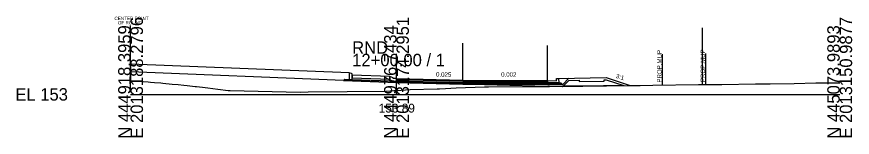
# Model space of a CAD drawing. Extents: x -26 to 163, y -10 to 7518.
# Drawn here: x -25.7 to 162.8, y 3990.3 to 4017.5 of the extents above; entities that cross this region are included whole.
import ezdxf

# ---------------------------------------------------------------- set-up
doc = ezdxf.new("R2010")
doc.units = 0
for name, color, linetype in [('Exist Cross Section Cell', 7, 'Continuous'), ('Exist XS Center Line Elevation Label', 7, 'Continuous'), ('Exist XS Ground Line', 7, 'Continuous'), ('Prop CMT Conc Surface', 7, 'Continuous'), ('Prop CMT Concrete Structures', 7, 'Continuous'), ('Prop CMT Pvmt Course 1', 7, 'Continuous'), ('Prop CMT Pvmt Course 1 CG', 7, 'Continuous'), ('Prop CMT Pvmt Course 2', 7, 'Continuous'), ('Prop CMT Pvmt Course 3', 7, 'Continuous'), ('Prop CMT Pvmt Surface', 7, 'Continuous'), ('Prop CMT Shear Line', 7, 'Continuous'), ('Prop CMT Shear Line Text', 7, 'Continuous'), ('Prop CMT Slope Grass', 7, 'Continuous'), ('Prop CMT Subgrade Earthwork', 7, 'Continuous'), ('Prop XS Earthwork Shape', 7, 'Continuous'), ('Prop XS Label Text', 7, 'Continuous'), ('Prop XS SE Text', 7, 'Continuous'), ('Prop XS Side Slope Text', 7, 'Continuous'), ('Scratch_Level_1', 7, 'Continuous')]:
    doc.layers.add(name, color=color, linetype=linetype)

msp = doc.modelspace()

# ---------------------------------------------------------------- linework, layer by layer
at = {"layer": 'Exist Cross Section Cell'}
for p, q in [((60, 4000), (60, 4009.16)), ((0, 4000), (60, 4000)), ((60, 4000), (160, 4000))]:
    msp.add_line(p, q, dxfattribs=at)
at = {"layer": 'Exist XS Ground Line'}
msp.add_lwpolyline([(0, 4003.05), (0.57, 4003.02), (1.73, 4002.95), (3.95, 4002.8), (4.51, 4002.76), (5.41, 4002.69), (6.86, 4002.58), (7.31, 4002.53), (9.41, 4002.32), (10.72, 4002.2), (11.98, 4002.07), (12.8, 4001.98), (14.56, 4001.8), (14.89, 4001.76), (16.21, 4001.62), (17.42, 4001.48), (19.69, 4001.2), (21.99, 4000.89), (22.46, 4000.88), (38.27, 4000.53), (40.04, 4000.58), (57.64, 4000.7), (59.4, 4000.86), (60, 4000.89), (63.11, 4001.07), (69.14, 4001.25), (69.71, 4001.28), (71.07, 4001.36), (73.47, 4001.46), (79.85, 4001.67), (80.43, 4001.69), (80.75, 4001.7), (90.04, 4001.77), (97.46, 4001.82), (99.61, 4001.83), (102.06, 4001.85), (112.76, 4001.99), (114.96, 4002.01), (117.85, 4002.05), (128.12, 4002.2), (133.39, 4002.25), (141.01, 4002.35), (144.34, 4002.37), (149.76, 4002.48), (154.62, 4002.57), (160, 4002.61)], dxfattribs=at)
at = {"layer": 'Prop CMT Conc Surface'}
for points in [[(50, 4004.54), (49.96, 4004.65), (49.85, 4004.69), (49.34, 4004.88)], [(50, 4004.38), (50, 4004.54)], [(60, 4003.58), (59.25, 4003.6), (59.25, 4003.77), (58.5, 4004.02)], [(94.09, 4003.16), (96.08, 4003.08)], [(96.08, 4003.08), (96.07, 4003.58), (96.57, 4003.59)]]:
    msp.add_lwpolyline(points, dxfattribs=at)
at = {"layer": 'Prop CMT Concrete Structures'}
for points in [[(50, 4004.54), (49.96, 4004.65), (49.85, 4004.69), (49.34, 4004.88)], [(49.34, 4004.88), (49.34, 4003.38)], [(50, 4004.38), (50, 4004.54)], [(49.34, 4003.38), (50, 4003.38)], [(50, 4003.38), (50, 4004.38)], [(50, 4004.38), (50, 4003.79)], [(58.5, 4004.02), (50, 4004.36)], [(50, 4003.77), (58.5, 4003.43)], [(60, 4003.58), (59.25, 4003.6), (59.25, 4003.77), (58.5, 4004.02)], [(58.5, 4004.02), (58.5, 4003.04)], [(58.5, 4003.43), (58.5, 4004.02)], [(58.5, 4003.04), (60, 4003)], [(60, 4003), (60, 4003.58)], [(94.09, 4003.16), (96.08, 4003.08), (96.07, 4003.58), (96.57, 4003.59)], [(96.57, 4003.59), (96.59, 4002.57), (94.09, 4002.58)], [(94.09, 4002.58), (94.09, 4003.16)]]:
    msp.add_lwpolyline(points, dxfattribs=at)
at = {"layer": 'Prop CMT Pvmt Course 1'}
for points in [[(60, 4003.58), (75, 4003.2)], [(60, 4003.33), (60, 4003.58)], [(75, 4002.95), (60, 4003.33)], [(75, 4003.2), (94.09, 4003.16)], [(94.09, 4002.91), (75.01, 4002.95)], [(94.09, 4003.16), (94.09, 4002.91)]]:
    msp.add_lwpolyline(points, dxfattribs=at)
msp.add_lwpolyline([(60, 4003.33), (60, 4003.46), (60, 4003.46), (60, 4003.33)], close=True, dxfattribs=at)
at = {"layer": 'Prop CMT Pvmt Course 1 CG'}
for points in [[(60, 4002.66), (60, 4003)], [(94.09, 4002.58), (97.09, 4002.57), (97.44, 4002.24)], [(94.09, 4002.24), (94.09, 4002.58)], [(97.52, 4002.24), (94.11, 4002.24)]]:
    msp.add_lwpolyline(points, dxfattribs=at)
at = {"layer": 'Prop CMT Pvmt Course 2'}
for points in [[(60, 4003), (60, 4003.33)], [(60, 4003.33), (75, 4002.95)], [(75, 4002.62), (60, 4003)], [(75.01, 4002.95), (94.09, 4002.91)], [(94.1, 4002.58), (75.01, 4002.62)], [(94.09, 4002.91), (94.09, 4002.58)]]:
    msp.add_lwpolyline(points, dxfattribs=at)
at = {"layer": 'Prop CMT Pvmt Course 3'}
for points in [[(50, 4003.38), (58.5, 4003.04)], [(60, 4003), (75, 4002.62)], [(60, 4002.66), (60, 4003)], [(75, 4002.29), (60, 4002.66)], [(75.01, 4002.62), (94.1, 4002.58)], [(94.09, 4002.58), (94.09, 4002.24)], [(94.11, 4002.24), (75.02, 4002.29)]]:
    msp.add_lwpolyline(points, dxfattribs=at)
at = {"layer": 'Prop CMT Pvmt Surface'}
for points in [[(60, 4003.58), (75, 4003.2)], [(75, 4003.2), (94.09, 4003.16)]]:
    msp.add_lwpolyline(points, dxfattribs=at)
at = {"layer": 'Prop CMT Shear Line'}
msp.add_line((0, 4000.52), (0, 4015.52), dxfattribs=at)
at = {"layer": 'Prop CMT Slope Grass'}
for p, q in [((49.34, 4004.86), (0, 4006.83)), ((48.06, 4003.14), (0, 4005.07))]:
    msp.add_line(p, q, dxfattribs=at)
for points in [[(96.57, 4003.59), (107.3, 4003.8)], [(107.3, 4003.8), (112.73, 4001.99)]]:
    msp.add_lwpolyline(points, dxfattribs=at)
at = {"layer": 'Prop CMT Subgrade Earthwork'}
for p, q in [((0, 4006.83), (0, 4003.05)), ((48.34, 4003.42), (48.06, 4003.14))]:
    msp.add_line(p, q, dxfattribs=at)
for points in [[(48.06, 4003.14), (60, 4002.66)], [(48.34, 4003.42), (49.34, 4003.38)], [(60, 4002.66), (75, 4002.29)], [(94.11, 4002.24), (97.52, 4002.24), (98.85, 4003.63)], [(75.02, 4002.29), (94.11, 4002.24)]]:
    msp.add_lwpolyline(points, dxfattribs=at)
at = {"layer": 'Prop XS Earthwork Shape'}
for points in [[(5.41, 4002.69), (6.86, 4002.58), (7.31, 4002.53), (9.41, 4002.32), (10.72, 4002.2), (11.98, 4002.07), (12.8, 4001.98), (14.56, 4001.8), (14.89, 4001.76), (16.21, 4001.62), (17.42, 4001.48), (19.69, 4001.2), (21.99, 4000.89), (22.46, 4000.88), (38.27, 4000.53), (40.04, 4000.58), (57.64, 4000.7), (59.4, 4000.86), (60, 4000.89), (63.11, 4001.07), (69.14, 4001.25), (69.71, 4001.28), (71.07, 4001.36), (73.47, 4001.46), (79.85, 4001.67), (80.43, 4001.69), (80.75, 4001.7), (90.04, 4001.77), (94.55, 4001.8), (94.08, 4001.81), (60, 4002.66), (48.06, 4003.14), (0, 4005.07), (0, 4003.05), (0.57, 4003.02), (1.73, 4002.95), (3.95, 4002.8), (4.51, 4002.76)], [(98.91, 4003.14), (101.22, 4003.2), (101.23, 4002.87), (106.85, 4002.98), (106.84, 4003.31), (107.3, 4003.31), (111.32, 4001.97), (102.06, 4001.85), (99.61, 4001.83), (97.59, 4001.82)], [(94.55, 4001.8), (97.46, 4001.82), (97.59, 4001.82), (97.49, 4001.72)]]:
    msp.add_lwpolyline(points, close=True, dxfattribs=at)
at = {"layer": 'Prop XS Label Text'}
for p, q in [((119.93, 4009.08), (119.93, 4002.08)), ((129.71, 4009.22), (129.71, 4002.22))]:
    msp.add_line(p, q, dxfattribs=at)
at = {"layer": 'Scratch_Level_1'}
for p, q in [((129.08, 4002.21), (129.08, 4015.01)), ((75, 4003.2), (75, 4011.55)), ((94.08, 4002.75), (94.08, 4011.03)), ((75, 4003.2), (94.08, 4003.16))]:
    msp.add_line(p, q, dxfattribs=at)

# ---------------------------------------------------------------- texts
at = {"layer": 'Exist Cross Section Cell'}
for s, p in [('E 2013188.2796', (2.8, 3990)), ('E 2013174.2951', (62.8, 3990)), ('E 2013150.9877', (162.8, 3990)), ('N 444918.3959', (0, 3990)), ('N 444976.7434', (60, 3990)), ('N 445073.9893', (160, 3990))]:
    msp.add_text(s, height=2.8, rotation=90, dxfattribs=at).set_placement(p)
for s, p in [('RND', (50, 4009.16)), ('12+00.00 / 1', (50, 4006.36)), ('EL 153', (-26, 3998.6))]:
    msp.add_text(s, height=2.8, dxfattribs=at).set_placement(p)
at = {"layer": 'Exist XS Center Line Elevation Label'}
msp.add_text('153.89', height=2, dxfattribs=at).set_placement((55.97, 3995.89))
at = {"layer": 'Prop CMT Shear Line Text'}
for s, p in [('CENTER POINT', (-3.64, 4016.78)), ('OF ROUND', (-2.88, 4015.8))]:
    msp.add_text(s, height=0.75, dxfattribs=at).set_placement(p)
at = {"layer": 'Prop XS Label Text'}
for p in [(119.83, 4002.66), (129.61, 4002.79)]:
    msp.add_text('PROP.MUP', height=1, rotation=90, dxfattribs=at).set_placement(p)
at = {"layer": 'Prop XS SE Text'}
for s, rotation, p in [('0.025', 358.5613, (68.91, 4004.04)), ('0.002', 359.867, (83.61, 4004))]:
    msp.add_text(s, height=1, rotation=rotation, dxfattribs=at).set_placement(p)
at = {"layer": 'Prop XS Side Slope Text'}
msp.add_text('3:1', height=1, rotation=342.8688, dxfattribs=at).set_placement((109.38, 4003.75))

doc.saveas('drawing.dxf')
